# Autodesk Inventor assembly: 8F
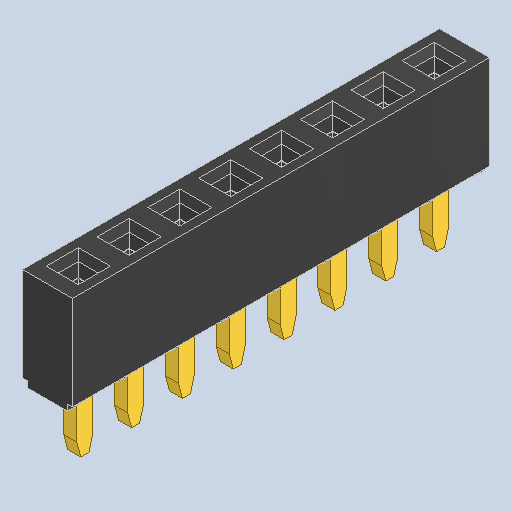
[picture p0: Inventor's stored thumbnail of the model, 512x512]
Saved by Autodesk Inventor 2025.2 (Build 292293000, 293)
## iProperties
Created: 2025-04
Part Number: 8F
Description: PART--DESC
Document SubType Name: Assembly
Designer: BennF
Author: BennF
Revision Number: NONE
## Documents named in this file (3)
- C:\Users\BennF\Nextcloud\Benutzer\CNC JarBeRi\existing parts\Electronics\RepRap A4988 Shied (USE WITHOUT ARDUINO)\reprap-a4988-1.snapshot.1\RepRap\RepRap\8F_3.iam
- C:\Users\BennF\Nextcloud\Benutzer\CNC JarBeRi\existing parts\Electronics\RepRap A4988 Shied (USE WITHOUT ARDUINO)\reprap-a4988-1.snapshot.1\RepRap\RepRap\8F Geometry.ipt
- C:\Users\BennF\Nextcloud\Benutzer\CNC JarBeRi\existing parts\Electronics\RepRap A4988 Shied (USE WITHOUT ARDUINO)\reprap-a4988-1.snapshot.1\RepRap\RepRap\Pin3.ipt
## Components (2 placed, 2 different names)
1. 8F Geometry
2. Pin3
